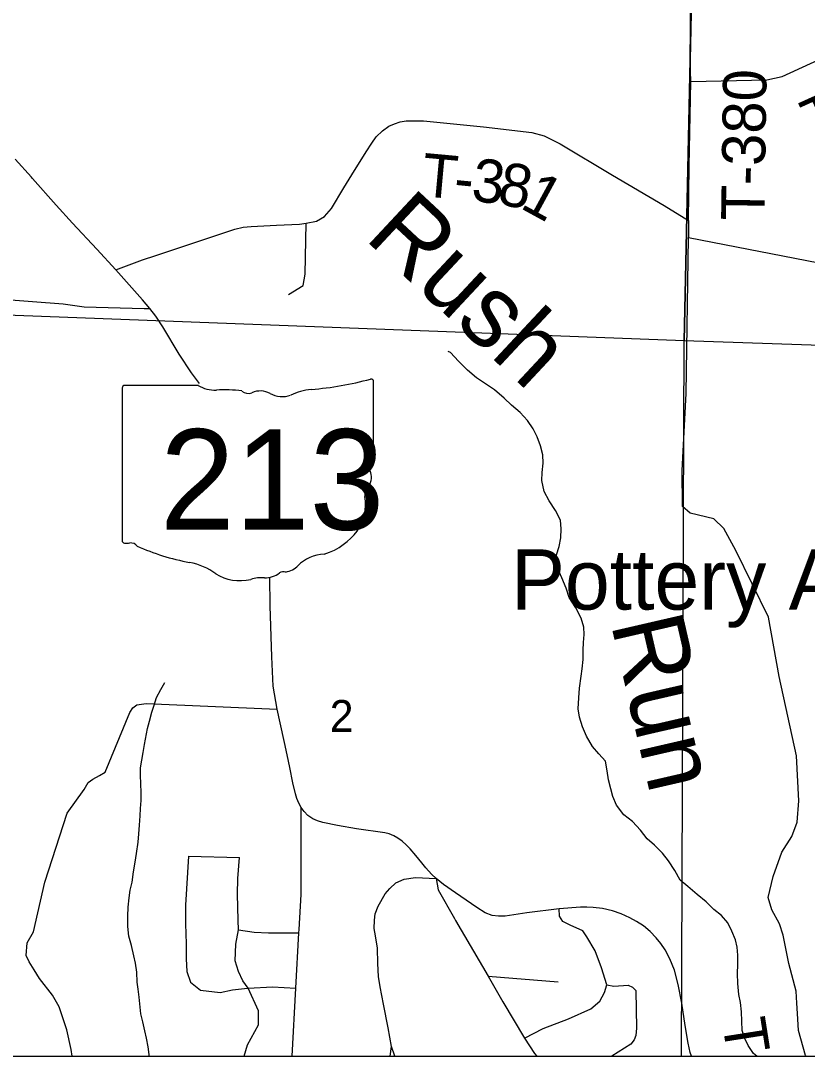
# Model space of a CAD drawing. Extents: x 2.1 to 8.9, y 14.1 to 20.9.
# Drawn here: x 5.524 to 6.556, y 14.1 to 15.459 of the extents above; entities that cross this region are included whole.
import ezdxf

# ---------------------------------------------------------------- set-up
doc = ezdxf.new("R2010")
doc.units = 0
for name, color, linetype in [('Default', 7, 'Continuous'), ('GM_X_City_Street', 7, 'Continuous'), ('GM_X_County_Road', 7, 'Continuous'), ('GM_X_County_Road_Text', 7, 'Continuous'), ('GM_X_Interchange_Ramps', 7, 'Continuous'), ('GM_X_Major_River', 7, 'Continuous'), ('GM_X_Minor_River_Text', 7, 'Continuous'), ('GM_X_Rail_Line_Text', 7, 'Continuous'), ('GM_X_Section_Text', 7, 'Continuous'), ('PV_P_Text', 7, 'Continuous'), ('SH_Cut_Line', 7, 'Continuous'), ('SH_Data', 7, 'Continuous'), ('TX_P_Misc', 7, 'Continuous')]:
    doc.layers.add(name, color=color, linetype=linetype)

msp = doc.modelspace()

# ---------------------------------------------------------------- linework, layer by layer
at = {"layer": 'Default'}
for p, q in [((6.3944, 15.0386), (5.4229, 15.0756)), ((6.3909, 14.1), (6.3944, 15.0386)), ((2.1, 14.1), (6.7017, 14.1)), ((5.3878, 14.1), (6.3909, 14.1))]:
    msp.add_line(p, q, dxfattribs=at)
at = {"layer": 'GM_X_City_Street'}
for p, q in [((6.4023, 15.4071), (6.4031, 15.5071)), ((6.5227, 15.3856), (6.6675, 15.4522)), ((6.4027, 15.3924), (6.4023, 15.4071)), ((6.4031, 15.379), (6.4027, 15.3924)), ((6.4031, 15.379), (6.5026, 15.3809)), ((6.5026, 15.3809), (6.5227, 15.3856)), ((6.4011, 15.2676), (6.4031, 15.379)), ((6.0217, 15.3259), (6.0299, 15.3271)), ((6.0299, 15.3271), (6.0375, 15.3274)), ((6.0375, 15.3274), (6.0527, 15.3271)), ((6.0527, 15.3271), (6.131, 15.3194)), ((5.9906, 15.3062), (5.9986, 15.3141)), ((5.9986, 15.3141), (6.007, 15.3201)), ((6.007, 15.3201), (6.0143, 15.3233)), ((6.0143, 15.3233), (6.0217, 15.3259)), ((6.131, 15.3194), (6.1944, 15.3118)), ((5.9846, 15.2979), (5.9906, 15.3062)), ((6.1944, 15.3118), (6.2106, 15.3074)), ((6.2106, 15.3074), (6.2316, 15.2969)), ((5.9585, 15.2563), (5.9775, 15.2867)), ((5.9775, 15.2867), (5.9846, 15.2979)), ((6.2316, 15.2969), (6.3003, 15.256)), ((6.3998, 15.1967), (6.4011, 15.2676)), ((5.9482, 15.2395), (5.9585, 15.2563)), ((6.3003, 15.256), (6.368, 15.2162)), ((5.9317, 15.2124), (5.9482, 15.2395)), ((5.9226, 15.2018), (5.9317, 15.2124)), ((6.368, 15.2162), (6.3998, 15.1967)), ((5.8266, 15.1888), (5.8596, 15.1905)), ((5.8596, 15.1905), (5.8901, 15.1919)), ((5.8901, 15.1919), (5.8987, 15.1928)), ((5.8973, 15.126), (5.8987, 15.1928)), ((5.8987, 15.1928), (5.9121, 15.1955)), ((5.9121, 15.1955), (5.9226, 15.2018)), ((6.3998, 15.1967), (6.3998, 15.187)), ((5.7017, 15.1508), (5.805, 15.1852)), ((5.805, 15.1852), (5.8162, 15.1876)), ((5.8162, 15.1876), (5.8266, 15.1888)), ((6.3998, 15.187), (6.4001, 15.1741)), ((6.397, 14.9697), (6.4001, 15.1741)), ((6.4001, 15.1741), (6.7213, 15.1117)), ((5.6839, 15.1447), (5.7017, 15.1508)), ((5.649, 15.1316), (5.6839, 15.1447)), ((5.8949, 15.1112), (5.8973, 15.126)), ((5.8754, 15.0995), (5.8949, 15.1112)), ((5.4575, 15.0963), (5.58, 15.0873)), ((5.58, 15.0873), (5.6074, 15.0831)), ((5.6074, 15.0831), (5.6864, 15.0811)), ((5.6864, 15.0811), (5.6935, 15.0809)), ((6.3917, 14.8684), (6.397, 14.9697)), ((6.3921, 14.8215), (6.3917, 14.8684)), ((6.4023, 14.8125), (6.3921, 14.8215)), ((6.4334, 14.8052), (6.4023, 14.8125)), ((6.4464, 14.7925), (6.4334, 14.8052)), ((6.4619, 14.7635), (6.4464, 14.7925)), ((6.5048, 14.6762), (6.4619, 14.7635)), ((6.5189, 14.5984), (6.5048, 14.6762)), ((6.5416, 14.4943), (6.5189, 14.5984)), ((5.6673, 14.5509), (5.6714, 14.5573)), ((5.6714, 14.5573), (5.6768, 14.5612)), ((5.6768, 14.5612), (5.6888, 14.563)), ((5.6888, 14.563), (5.8604, 14.5555)), ((5.635, 14.4726), (5.6673, 14.5509)), ((6.5449, 14.435), (6.5416, 14.4943)), ((5.6276, 14.4683), (5.635, 14.4726)), ((5.6074, 14.4502), (5.6129, 14.4591)), ((5.6129, 14.4591), (5.6189, 14.4634)), ((5.6189, 14.4634), (5.6276, 14.4683)), ((5.5853, 14.4191), (5.6074, 14.4502)), ((6.5425, 14.4071), (6.5449, 14.435)), ((5.5559, 14.3282), (5.5853, 14.4191)), ((5.892, 14.3121), (5.8923, 14.4262)), ((6.5356, 14.3885), (6.5425, 14.4071)), ((6.5222, 14.3676), (6.5356, 14.3885)), ((5.7444, 14.3625), (5.7404, 14.2984)), ((5.7444, 14.3625), (5.8113, 14.3609)), ((6.5112, 14.3359), (6.5222, 14.3676)), ((5.8089, 14.333), (5.8113, 14.3609)), ((6.0272, 14.3324), (6.042, 14.3347)), ((6.042, 14.3347), (6.069, 14.3331)), ((6.5046, 14.3081), (6.5112, 14.3359)), ((5.541, 14.2632), (5.5559, 14.3282)), ((5.8085, 14.3125), (5.8089, 14.333)), ((6.0085, 14.3201), (6.0163, 14.3276)), ((6.0163, 14.3276), (6.0272, 14.3324)), ((6.069, 14.3331), (6.0719, 14.3182)), ((5.8093, 14.2787), (5.8085, 14.3125)), ((5.8895, 14.2664), (5.892, 14.3121)), ((5.9931, 14.2969), (6.0021, 14.3129)), ((6.0021, 14.3129), (6.0085, 14.3201)), ((6.0719, 14.3182), (6.0932, 14.2807)), ((6.5091, 14.2922), (6.5046, 14.3081)), ((5.7404, 14.2984), (5.7404, 14.2736)), ((5.9892, 14.2869), (5.9931, 14.2969)), ((6.231, 14.2838), (6.2306, 14.2935)), ((5.9883, 14.2786), (5.9892, 14.2869)), ((6.0932, 14.2807), (6.0946, 14.2782)), ((6.2351, 14.277), (6.231, 14.2838)), ((6.5194, 14.2737), (6.5091, 14.2922)), ((5.7404, 14.2736), (5.7412, 14.2476)), ((5.8101, 14.2657), (5.8093, 14.2787)), ((5.8892, 14.2618), (5.8895, 14.2664)), ((5.9876, 14.2677), (5.9883, 14.2786)), ((5.9896, 14.2578), (5.9876, 14.2677)), ((6.0946, 14.2782), (6.1372, 14.2049)), ((6.2448, 14.2722), (6.2351, 14.277)), ((6.2613, 14.2646), (6.2448, 14.2722)), ((6.5242, 14.2589), (6.5194, 14.2737)), ((5.533, 14.2488), (5.541, 14.2632)), ((5.8066, 14.2472), (5.8101, 14.2657)), ((5.8101, 14.2657), (5.8306, 14.2629)), ((5.8306, 14.2629), (5.8491, 14.2621)), ((5.8491, 14.2621), (5.8892, 14.2618)), ((5.8853, 14.1893), (5.8892, 14.2618)), ((5.9924, 14.2417), (5.9896, 14.2578)), ((6.2668, 14.2568), (6.2613, 14.2646)), ((6.2774, 14.2381), (6.2668, 14.2568)), ((6.5315, 14.2217), (6.5242, 14.2589)), ((5.5316, 14.2321), (5.533, 14.2488)), ((5.7412, 14.2476), (5.7412, 14.2279)), ((5.8054, 14.2252), (5.8066, 14.2472)), ((5.9928, 14.2215), (5.9924, 14.2417)), ((5.5354, 14.2241), (5.5316, 14.2321)), ((5.7412, 14.2279), (5.742, 14.211)), ((6.286, 14.216), (6.2774, 14.2381)), ((5.5421, 14.2136), (5.5354, 14.2241)), ((5.549, 14.2021), (5.5421, 14.2136)), ((5.8101, 14.211), (5.8054, 14.2252)), ((5.9936, 14.2047), (5.9928, 14.2215)), ((6.2928, 14.1939), (6.286, 14.216)), ((6.5414, 14.1853), (6.5315, 14.2217)), ((5.5659, 14.1802), (5.549, 14.2021)), ((5.742, 14.211), (5.7471, 14.1972)), ((5.8158, 14.1989), (5.8101, 14.211)), ((5.8227, 14.1893), (5.8158, 14.1989)), ((5.9958, 14.1912), (5.9936, 14.2047)), ((6.1372, 14.2049), (6.229, 14.1978)), ((6.1372, 14.2049), (6.1565, 14.1713)), ((5.7471, 14.1972), (5.7601, 14.1866)), ((5.7601, 14.1866), (5.7859, 14.1835)), ((5.7859, 14.1835), (5.8022, 14.187)), ((5.8022, 14.187), (5.8178, 14.1888)), ((5.8178, 14.1888), (5.8227, 14.1893)), ((5.8227, 14.1893), (5.8546, 14.1913)), ((5.8361, 14.1598), (5.8227, 14.1893)), ((5.8546, 14.1913), (5.8853, 14.1893)), ((5.8805, 14.1), (5.8853, 14.1893)), ((6.0001, 14.1685), (5.9958, 14.1912)), ((6.2897, 14.1837), (6.2928, 14.1939)), ((6.2928, 14.1939), (6.3019, 14.1921)), ((6.3019, 14.1921), (6.3208, 14.1932)), ((6.3208, 14.1932), (6.3264, 14.1907)), ((6.3264, 14.1907), (6.3309, 14.1864)), ((6.3309, 14.1864), (6.3317, 14.1369)), ((6.5422, 14.1698), (6.5414, 14.1853)), ((5.5747, 14.165), (5.5659, 14.1802)), ((6.1565, 14.1713), (6.1848, 14.1237)), ((6.2718, 14.1622), (6.2839, 14.1723)), ((6.2839, 14.1723), (6.2897, 14.1837)), ((5.5848, 14.1347), (5.5747, 14.165)), ((5.8363, 14.1411), (5.8361, 14.1598)), ((6.0062, 14.1372), (6.0001, 14.1685)), ((6.2425, 14.1489), (6.2718, 14.1622)), ((6.5429, 14.1563), (6.5422, 14.1698)), ((6.2096, 14.1364), (6.2425, 14.1489)), ((6.5441, 14.1336), (6.5429, 14.1563)), ((5.5903, 14.109), (5.5848, 14.1347)), ((5.8219, 14.1148), (5.8363, 14.1411)), ((6.0107, 14.1127), (6.0062, 14.1372)), ((6.1848, 14.1237), (6.2096, 14.1364)), ((6.3317, 14.1369), (6.3308, 14.1273)), ((6.5536, 14.1008), (6.5441, 14.1336)), ((6.1848, 14.1237), (6.198, 14.1038)), ((6.3289, 14.1217), (6.3243, 14.1158)), ((6.3308, 14.1273), (6.3289, 14.1217)), ((5.5917, 14.1), (5.5903, 14.109)), ((5.8174, 14.1), (5.8219, 14.1148)), ((6.0086, 14.1), (6.0107, 14.1127)), ((6.0148, 14.1), (6.0107, 14.1127)), ((6.198, 14.1038), (6.201, 14.1)), ((6.3243, 14.1158), (6.2993, 14.1)), ((6.5541, 14.1), (6.5536, 14.1008))]:
    msp.add_line(p, q, dxfattribs=at)
at = {"layer": 'GM_X_County_Road'}
for p, q in [((5.6575, 14.9768), (5.6575, 14.7766)), ((5.7573, 14.9802), (5.6607, 14.9802)), ((5.9871, 14.8805), (5.9871, 14.9852)), ((5.987, 14.8805), (5.9871, 14.8805))]:
    msp.add_line(p, q, dxfattribs=at)
for centre, major_axis, start_param, end_param in [((5.8697, 15.253), (0.3495, 0), 4.814394, 5.042369), ((5.9834, 14.9856), (0.00367, 0), 6.141152, 7.989035), ((5.6613, 14.9772), (0.00382, 0), 1.712693, 3.28349), ((5.7802, 15.0034), (0.037, 0), 4.042888, 4.731795), ((5.7925, 14.8679), (0.133, 0), 1.404758, 1.657858), ((5.8227, 14.9782), (0.0107, 0), 3.836095, 5.185415), ((5.8384, 14.9551), (0.0222, 0), 0.950623, 2.079405), ((5.9143, 14.9191), (0.0703, 0), 1.699011, 2.107814), ((5.8671, 14.9868), (0.0267, 0), 4.081561, 5.145723), ((5.9832, 14.8801), (0.00393, 0), 5.05454, 6.418171), ((5.9862, 14.8728), (0.00568, 0), 1.883978, 3.671073), ((5.9501, 14.8596), (0.0341, 0), 5.934695, 6.695948), ((6.0002, 14.8367), (0.0248, 0), 2.387724, 3.262537), ((5.8892, 14.8234), (0.0874, 0), 5.101752, 6.440018), ((5.6613, 14.7762), (0.00385, 0), 3.00124, 4.508301), ((5.6619, 14.7967), (0.0294, 0), 4.665946, 4.897461), ((5.6679, 14.7651), (0.0106, 0), 0.519207, 1.627899), ((5.8017, 14.9449), (0.2524, 0), 4.195997, 4.488961), ((5.9261, 14.7205), (0.0479, 0), 1.647645, 2.488434), ((5.7265, 14.6867), (0.079, 0), 0.823519, 1.323587), ((5.8654, 14.7573), (0.0282, 0), 4.937069, 5.64225), ((5.8119, 14.7641), (0.0501, 0), 4.026481, 4.996735), ((5.8408, 14.6949), (0.0412, 0), 1.495662, 1.94098), ((5.8445, 14.7491), (0.0267, 0), 4.691044, 5.507374), ((5.8687, 14.7297), (0.00752, 0), 1.147584, 2.315152)]:
    msp.add_ellipse(centre, major_axis=major_axis, ratio=0.8, start_param=start_param, end_param=end_param, dxfattribs=at)
at = {"layer": 'GM_X_Interchange_Ramps'}
for p, q in [((6.4161, 16.0534), (6.3944, 15.0386)), ((6.3944, 15.0386), (6.4161, 16.0534)), ((6.3944, 15.0386), (5.4229, 15.0756)), ((7.348, 15.0053), (6.3944, 15.0386))]:
    msp.add_line(p, q, dxfattribs=at)
at = {"layer": 'GM_X_Rail_Line_Text'}
for p, q in [((5.5383, 15.2533), (5.5171, 15.2768)), ((5.5397, 15.2518), (5.5383, 15.2533)), ((5.5707, 15.2166), (5.5397, 15.2518)), ((5.5921, 15.1931), (5.5707, 15.2166)), ((5.6243, 15.1591), (5.5921, 15.1931)), ((5.649, 15.1316), (5.6243, 15.1591)), ((5.6839, 15.0925), (5.649, 15.1316)), ((5.6935, 15.0809), (5.6839, 15.0925)), ((5.7015, 15.0708), (5.6935, 15.0809)), ((5.7109, 15.057), (5.7015, 15.0708)), ((5.7323, 15.021), (5.7109, 15.057)), ((5.7484, 14.9968), (5.7323, 15.021)), ((5.7587, 14.9827), (5.7484, 14.9968)), ((5.8516, 14.6909), (5.8509, 14.7284)), ((5.8537, 14.6242), (5.8516, 14.6909)), ((5.8552, 14.5856), (5.8537, 14.6242)), ((5.8604, 14.5555), (5.8552, 14.5856)), ((5.8645, 14.5376), (5.8604, 14.5555)), ((5.8704, 14.5116), (5.8645, 14.5376)), ((5.8739, 14.4953), (5.8704, 14.5116)), ((5.8773, 14.4788), (5.8739, 14.4953)), ((5.8813, 14.4587), (5.8773, 14.4788)), ((5.8846, 14.4443), (5.8813, 14.4587)), ((5.8865, 14.438), (5.8846, 14.4443)), ((5.889, 14.4321), (5.8865, 14.438)), ((5.8923, 14.4262), (5.889, 14.4321)), ((5.8961, 14.421), (5.8923, 14.4262)), ((5.901, 14.4159), (5.8961, 14.421)), ((5.9074, 14.4116), (5.901, 14.4159)), ((5.9135, 14.4087), (5.9074, 14.4116)), ((5.9207, 14.4065), (5.9135, 14.4087)), ((5.9398, 14.4026), (5.9207, 14.4065)), ((5.9646, 14.3983), (5.9398, 14.4026)), ((6.0017, 14.3931), (5.9646, 14.3983)), ((6.0076, 14.3916), (6.0017, 14.3931)), ((6.0134, 14.3894), (6.0076, 14.3916)), ((6.0189, 14.3862), (6.0134, 14.3894)), ((6.0244, 14.3823), (6.0189, 14.3862)), ((6.0299, 14.3774), (6.0244, 14.3823)), ((6.0349, 14.3722), (6.0299, 14.3774)), ((6.0425, 14.3635), (6.0349, 14.3722)), ((6.0503, 14.3536), (6.0425, 14.3635)), ((6.0556, 14.347), (6.0503, 14.3536)), ((6.0629, 14.3389), (6.0556, 14.347)), ((6.069, 14.3331), (6.0629, 14.3389)), ((6.0789, 14.3253), (6.069, 14.3331)), ((6.0946, 14.3142), (6.0789, 14.3253)), ((6.1225, 14.295), (6.0946, 14.3142)), ((6.1334, 14.2883), (6.1225, 14.295)), ((6.2306, 14.2935), (6.1882, 14.288)), ((6.2582, 14.2958), (6.2306, 14.2935)), ((6.2667, 14.2958), (6.2582, 14.2958)), ((6.275, 14.2952), (6.2667, 14.2958)), ((6.2874, 14.2939), (6.275, 14.2952)), ((6.3003, 14.2907), (6.2874, 14.2939)), ((6.1426, 14.2847), (6.1334, 14.2883)), ((6.1508, 14.2837), (6.1426, 14.2847)), ((6.1595, 14.2838), (6.1508, 14.2837)), ((6.1882, 14.288), (6.1595, 14.2838)), ((6.3118, 14.2867), (6.3003, 14.2907)), ((6.3229, 14.2817), (6.3118, 14.2867)), ((6.3319, 14.2769), (6.3229, 14.2817)), ((6.3411, 14.271), (6.3319, 14.2769)), ((6.3498, 14.2635), (6.3411, 14.271)), ((6.3578, 14.2555), (6.3498, 14.2635)), ((6.3638, 14.2481), (6.3578, 14.2555)), ((6.3695, 14.2395), (6.3638, 14.2481)), ((6.3756, 14.2276), (6.3695, 14.2395)), ((6.3815, 14.2129), (6.3756, 14.2276)), ((6.3866, 14.1942), (6.3815, 14.2129)), ((6.3913, 14.1696), (6.3866, 14.1942)), ((6.3955, 14.1402), (6.3913, 14.1696)), ((6.3996, 14.1172), (6.3955, 14.1402)), ((6.4021, 14.1051), (6.3996, 14.1172)), ((6.4038, 14.1), (6.4021, 14.1051))]:
    msp.add_line(p, q, dxfattribs=at)
at = {"layer": 'SH_Cut_Line'}
msp.add_line((2.1, 14.1), (6.7017, 14.1), dxfattribs=at)
at = {"layer": 'SH_Data'}
msp.add_line((2.1, 14.1), (8.9, 14.1), dxfattribs=at)
msp.add_line((2.1, 14.1), (8.9, 14.1), dxfattribs=at)
at = {"layer": 'TX_P_Misc'}
for p, q in [((6.0877, 15.0232), (6.085, 15.0246)), ((6.0986, 15.0121), (6.0877, 15.0232)), ((6.11, 15.0003), (6.0986, 15.0121)), ((6.1218, 14.9901), (6.11, 15.0003)), ((6.1338, 14.9821), (6.1218, 14.9901)), ((6.1455, 14.9744), (6.1338, 14.9821)), ((6.1583, 14.9634), (6.1455, 14.9744)), ((6.1681, 14.9542), (6.1583, 14.9634)), ((6.1791, 14.9447), (6.1681, 14.9542)), ((6.1889, 14.934), (6.1791, 14.9447)), ((6.1965, 14.9232), (6.1889, 14.934)), ((6.2014, 14.9127), (6.1965, 14.9232)), ((6.2059, 14.9007), (6.2014, 14.9127)), ((6.209, 14.889), (6.2059, 14.9007)), ((6.2082, 14.8658), (6.2093, 14.8783)), ((6.2093, 14.8783), (6.209, 14.889)), ((6.2077, 14.8555), (6.2082, 14.8658)), ((6.2109, 14.8408), (6.2077, 14.8555)), ((6.2173, 14.8288), (6.2109, 14.8408)), ((6.2257, 14.8161), (6.2173, 14.8288)), ((6.2322, 14.8034), (6.2257, 14.8161)), ((6.2329, 14.792), (6.2322, 14.8034)), ((6.2325, 14.7802), (6.2329, 14.792)), ((6.2306, 14.7688), (6.2325, 14.7802)), ((6.2248, 14.7484), (6.2268, 14.758)), ((6.2268, 14.758), (6.2306, 14.7688)), ((6.2338, 14.7278), (6.2248, 14.7484)), ((6.2395, 14.7143), (6.2338, 14.7278)), ((6.2437, 14.7019), (6.2395, 14.7143)), ((6.2521, 14.6884), (6.2437, 14.7019)), ((6.2594, 14.6746), (6.2521, 14.6884)), ((6.2628, 14.6629), (6.2594, 14.6746)), ((6.2631, 14.6534), (6.2628, 14.6629)), ((6.2623, 14.6428), (6.2631, 14.6534)), ((6.2619, 14.6329), (6.2623, 14.6428)), ((6.2607, 14.6085), (6.2619, 14.6207)), ((6.2619, 14.6207), (6.2619, 14.6329)), ((6.2591, 14.5986), (6.2607, 14.6085)), ((6.257, 14.5829), (6.2591, 14.5986)), ((5.7023, 14.5708), (5.708, 14.5813)), ((5.708, 14.5813), (5.7131, 14.5902)), ((6.2562, 14.5703), (6.257, 14.5829)), ((5.6992, 14.5608), (5.7023, 14.5708)), ((6.2555, 14.5559), (6.2562, 14.5703)), ((5.6964, 14.5513), (5.6992, 14.5608)), ((6.257, 14.5449), (6.2555, 14.5559)), ((5.6906, 14.5298), (5.6934, 14.5397)), ((5.6934, 14.5397), (5.6964, 14.5513)), ((6.2608, 14.5321), (6.257, 14.5449)), ((5.6867, 14.5091), (5.6906, 14.5298)), ((6.2662, 14.5201), (6.2608, 14.5321)), ((6.2742, 14.5063), (6.2662, 14.5201)), ((5.6816, 14.4785), (5.6848, 14.4984)), ((5.6848, 14.4984), (5.6867, 14.5091)), ((6.2825, 14.4966), (6.2742, 14.5063)), ((6.2912, 14.487), (6.2825, 14.4966)), ((6.2934, 14.4745), (6.2912, 14.487)), ((5.6815, 14.469), (5.6816, 14.4785)), ((6.295, 14.4628), (6.2934, 14.4745)), ((5.6822, 14.4462), (5.6815, 14.469)), ((6.298, 14.4507), (6.295, 14.4628)), ((5.6822, 14.4356), (5.6822, 14.4462)), ((6.3006, 14.4406), (6.298, 14.4507)), ((5.6814, 14.4249), (5.6822, 14.4356)), ((6.3055, 14.4293), (6.3006, 14.4406)), ((6.315, 14.4167), (6.3055, 14.4293)), ((5.6809, 14.4154), (5.6814, 14.4249)), ((6.3267, 14.4079), (6.315, 14.4167)), ((5.6794, 14.3918), (5.6802, 14.4032)), ((5.6802, 14.4032), (5.6809, 14.4154)), ((6.3369, 14.3968), (6.3267, 14.4079)), ((5.6782, 14.3807), (5.6794, 14.3918)), ((6.3457, 14.3853), (6.3369, 14.3968)), ((5.676, 14.3658), (5.6782, 14.3807)), ((6.3554, 14.3769), (6.3457, 14.3853)), ((6.3657, 14.3666), (6.3554, 14.3769)), ((5.6745, 14.3548), (5.676, 14.3658)), ((6.374, 14.3562), (6.3657, 14.3666)), ((5.6722, 14.3418), (5.6745, 14.3548)), ((6.3823, 14.3439), (6.374, 14.3562)), ((5.6704, 14.3284), (5.6722, 14.3418)), ((6.3892, 14.3312), (6.3823, 14.3439)), ((5.668, 14.3181), (5.6704, 14.3284)), ((6.399, 14.3227), (6.3892, 14.3312)), ((6.4115, 14.3121), (6.399, 14.3227)), ((5.6653, 14.2955), (5.6664, 14.3077)), ((5.6664, 14.3077), (5.668, 14.3181)), ((6.4232, 14.3026), (6.4115, 14.3121)), ((5.6649, 14.2837), (5.6653, 14.2955)), ((6.4334, 14.2926), (6.4232, 14.3026)), ((5.665, 14.2704), (5.6649, 14.2837)), ((6.4435, 14.2846), (6.4334, 14.2926)), ((6.4514, 14.275), (6.4435, 14.2846)), ((5.6661, 14.2575), (5.665, 14.2704)), ((6.4567, 14.2641), (6.4514, 14.275)), ((5.6695, 14.2451), (5.6661, 14.2575)), ((6.4616, 14.2528), (6.4567, 14.2641)), ((6.4638, 14.243), (6.4616, 14.2528)), ((5.6726, 14.2319), (5.6695, 14.2451)), ((6.4645, 14.2328), (6.4638, 14.243)), ((5.6748, 14.2221), (5.6726, 14.2319)), ((6.4645, 14.2206), (6.4645, 14.2328)), ((5.6767, 14.2103), (5.6748, 14.2221)), ((6.4641, 14.2084), (6.4645, 14.2206)), ((5.6771, 14.1974), (5.6767, 14.2103)), ((6.4649, 14.1955), (6.4641, 14.2084)), ((5.6782, 14.188), (5.6771, 14.1974)), ((5.6796, 14.1777), (5.6782, 14.188)), ((6.4661, 14.1811), (6.4649, 14.1955)), ((5.6819, 14.1558), (5.6796, 14.1777)), ((6.468, 14.1705), (6.4661, 14.1811)), ((6.4695, 14.1584), (6.468, 14.1705)), ((6.4703, 14.1337), (6.4695, 14.1584)), ((5.6845, 14.1452), (5.6819, 14.1558)), ((5.6871, 14.1335), (5.6845, 14.1452)), ((5.6893, 14.1237), (5.6871, 14.1335)), ((6.4736, 14.124), (6.4703, 14.1337)), ((5.6916, 14.1123), (5.6893, 14.1237)), ((6.4781, 14.1142), (6.4736, 14.124)), ((5.6927, 14.1021), (5.6916, 14.1123)), ((6.4853, 14.1038), (6.4781, 14.1142)), ((6.4895, 14.1), (6.4853, 14.1038)), ((5.6929, 14.1), (5.6927, 14.1021))]:
    msp.add_line(p, q, dxfattribs=at)

# ---------------------------------------------------------------- texts
at = {"layer": 'GM_X_County_Road'}
msp.add_text('213', height=0.13184, dxfattribs=at).set_placement((5.707, 14.7908))
at = {"layer": 'GM_X_County_Road_Text'}
msp.add_text('2', height=0.0419, rotation=0, dxfattribs=at).set_placement((5.9296, 14.5255))
at = {"layer": 'GM_X_Major_River'}
msp.add_text('Pottery Addition', height=0.078977, rotation=0, dxfattribs=at).set_placement((6.1675, 14.686))
at = {"layer": 'GM_X_Minor_River_Text'}
for s, height, rotation, p in [('T-582', 0.05682, 24.3044, (6.5656, 15.2978)), ('T-380', 0.05682, 89.1579, (6.4995, 15.1962)), ('T', 0.0568, 354.7602, (6.0486, 15.2286)), ('3', 0.0568, 353.2455, (6.1138, 15.2225)), ('8', 0.0568, 349.381, (6.1475, 15.2185)), ('-', 0.0568, 354.3865, (6.0908, 15.2248)), ('1', 0.0568, 331.3958, (6.1775, 15.2137)), ('T', 0.0568, 278.9762, (6.4438, 14.1456))]:
    msp.add_text(s, height=height, rotation=rotation, dxfattribs=at).set_placement(p)
at = {"layer": 'GM_X_Section_Text'}
for s in ['s', 'r']:
    msp.add_text(s, height=0.000189, dxfattribs=at).set_placement((5.8186, 14.8634))
msp.add_text('213', height=0.000189, rotation=0, dxfattribs=at).set_placement((5.7517, 14.8496))
at = {"layer": 'PV_P_Text'}
for s, height, rotation, p in [('Rush', 0.0947, 316.972, (5.9737, 15.173)), ('Run', 0.09467, 282.9749, (6.298, 14.668))]:
    msp.add_text(s, height=height, rotation=rotation, dxfattribs=at).set_placement(p)

doc.saveas('drawing.dxf')
